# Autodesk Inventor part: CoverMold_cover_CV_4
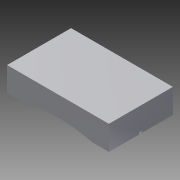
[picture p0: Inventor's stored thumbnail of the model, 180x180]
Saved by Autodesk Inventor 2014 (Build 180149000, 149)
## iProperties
Created: 2009-12
Part Number: CoverMold_cover_CV_4
Document SubType Name: Modeling
Designer: gaom
Density: 1 g/cm^3
Material: Generic
Appearance: Default
Author: gaom
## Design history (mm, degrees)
node "CoverMold_cover_CV_Base"
feature "Solid1::CoverMold_cover_CV_Base"
tag "TaggingFeature1"
body "Solid1"
